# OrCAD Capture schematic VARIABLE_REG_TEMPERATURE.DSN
size A
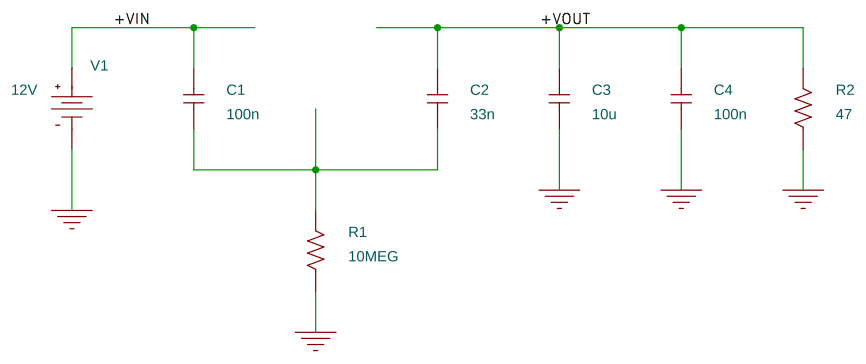
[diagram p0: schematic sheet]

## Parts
C1  100n  [RAD/CK05]
C2  33n  [RAD/CK05]
C3  10u  [RAD/CK05]
C4  100n  [RAD/CK05]
R1  10MEG  [AXRC05]
R2  47  [AXRC05]
V1  VDC

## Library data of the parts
C1 C4 = C: AppProp: InductiveSlave:;SRF:;PrevCap:100n;PrevESL:; ESR: 1m; IC: 0; Tolerance: 0.1
C2 = C: AppProp: InductiveSlave:;SRF:;PrevCap:33n;PrevESL:; ESR: 1m; IC: 0; Tolerance: .1
C3 = C: AppProp: InductiveSlave:;SRF:;PrevCap:10u;PrevESL:; ESR: 5m; IC: 0; Tolerance: 0.2
R1 R2 = R
V1 = VDC: DC: 12V

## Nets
+VIN: C1.2 V1.0(+)
0: C3.1 C4.1 R1.1 R2.1 V1.1(-)
+VOUT: C2.2 C3.2 C4.2 R2.2
N00170: C1.1 C2.1 R1.2
